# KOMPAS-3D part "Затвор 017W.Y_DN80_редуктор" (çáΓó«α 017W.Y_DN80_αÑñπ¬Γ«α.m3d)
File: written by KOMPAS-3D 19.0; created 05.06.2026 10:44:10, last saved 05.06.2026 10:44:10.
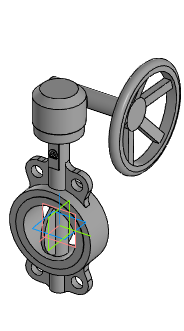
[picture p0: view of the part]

Document properties: Автор: Энергия; Полное имя файла: ..\..\..\3d для проектировщиков\x.x Тип 017W.Y(S) Затвор дисковый поворотный межфланцевый\Затвор 017W.Y(S)_DN50-DN1200_редуктор\Затвор 017W.Y_DN80_редуктор.a3d

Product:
- Part/product: Затвор 017W.Y_DN80_редуктор
    Масса: 6.87778

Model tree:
1. Операция без истории:1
